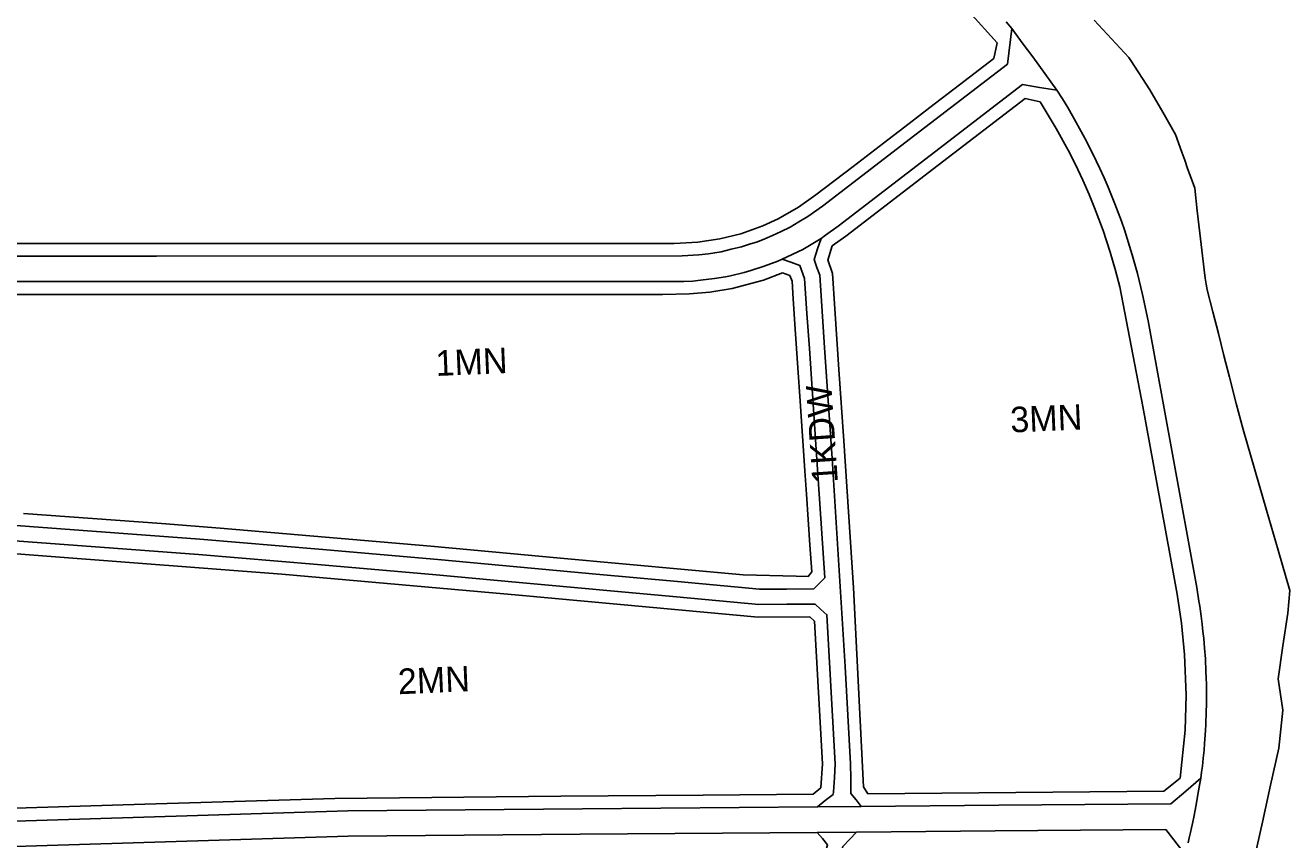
# Model space of a CAD drawing. Extents: x 7418021 to 7419743, y 5540231 to 5541685.
# Drawn here: x 7419247.1 to 7419743, y 5541025.9 to 5541345.6 of the extents above; entities that cross this region are included whole.
import ezdxf

# ---------------------------------------------------------------- set-up
doc = ezdxf.new("R2010")
doc.units = 0
for name, color, linetype in [('linie_rozgraniczajace', 7, 'Continuous'), ('linie_zabudowy_nieprzekraczalne', 7, 'Continuous'), ('oznaczenia_przeznaczen', 7, 'Continuous')]:
    doc.layers.add(name, color=color, linetype=linetype)

msp = doc.modelspace()

# ---------------------------------------------------------------- linework, layer by layer
at = {"layer": 'linie_rozgraniczajace'}
for points in [[(7419631.75, 5541346.86), (7419633.97, 5541344.26), (7419632.27, 5541330.34), (7419596.02, 5541302.47), (7419559.77, 5541274.61), (7419553.96, 5541270.48), (7419550.51, 5541268.42), (7419547.06, 5541266.36), (7419543.61, 5541264.67), (7419540.15, 5541262.98), (7419537.19, 5541261.79), (7419534.23, 5541260.6), (7419531.08, 5541259.59), (7419527.94, 5541258.57), (7419523.97, 5541257.62), (7419520, 5541256.67), (7419517.51, 5541256.26), (7419515.02, 5541255.84), (7419511.27, 5541255.47), (7419504.69, 5541255.01), (7419298.53, 5541254.95), (7419075.49, 5541254.87)], [(7419703.12, 5541024.71), (7419703.59, 5541026.71), (7419704.05, 5541028.71), (7419704.47, 5541030.52), (7419704.89, 5541032.32), (7419705.47, 5541035.46), (7419706.1, 5541038.89), (7419706.66, 5541041.98), (7419706.96, 5541043.61), (7419707.51, 5541046.59), (7419708.15, 5541050.07), (7419708.45, 5541052.45), (7419708.75, 5541054.84), (7419709.07, 5541057.94), (7419709.39, 5541061.04), (7419709.6, 5541063.73), (7419709.95, 5541068.8), (7419710.09, 5541071.18), (7419710.27, 5541076.32), (7419710.31, 5541078.79), (7419710.32, 5541084.06), (7419710.3, 5541086.86), (7419710.23, 5541089.41), (7419710.15, 5541091.96), (7419709.9, 5541096.87), (7419709.6, 5541101.12), (7419709.27, 5541104.88), (7419708.97, 5541107.68), (7419708.67, 5541110.48), (7419708.27, 5541113.65), (7419707.72, 5541117.53), (7419707.39, 5541119.59), (7419706.5, 5541124.88), (7419696.97, 5541177.21), (7419687.43, 5541229.54), (7419685.31, 5541239.93), (7419683.32, 5541248.08), (7419681.26, 5541255.49), (7419678.13, 5541265.27), (7419676.95, 5541268.73), (7419675.69, 5541272.12), (7419674.42, 5541275.5), (7419673.11, 5541278.74), (7419671.8, 5541281.97), (7419670.19, 5541285.63), (7419668.57, 5541289.28), (7419667.11, 5541292.34), (7419663.36, 5541299.83), (7419659.11, 5541307.71), (7419655.99, 5541313.27), (7419653.83, 5541316.68), (7419651.67, 5541320.09), (7419646.99, 5541326.58), (7419642.28, 5541333.11), (7419638.12, 5541338.69), (7419633.97, 5541344.26), (7419631.75, 5541346.86)], [(7419666.33, 5541347.56), (7419673.13, 5541340.23), (7419679.92, 5541332.9), (7419680.74, 5541331.7), (7419688.16, 5541320.18), (7419693.18, 5541311.45), (7419698.21, 5541302.72), (7419700.66, 5541295.81), (7419701.8, 5541292.6), (7419702.94, 5541289.4), (7419704.33, 5541285.49), (7419705.72, 5541281.59), (7419706.74, 5541272.76), (7419707.76, 5541263.94), (7419708.78, 5541255.12), (7419709.79, 5541246.29), (7419710.23, 5541244), (7419710.66, 5541241.7), (7419712.83, 5541233.14), (7419714.99, 5541224.58), (7419717.16, 5541216.01), (7419719.33, 5541207.45), (7419722.03, 5541197.17), (7419724.73, 5541186.88), (7419729.29, 5541171.09), (7419733.85, 5541155.31), (7419738.42, 5541139.52), (7419742.98, 5541123.73), (7419742.19, 5541114.89), (7419740.31, 5541101.99), (7419738.43, 5541089.08), (7419739.33, 5541082.91), (7419740.24, 5541076.74), (7419739.46, 5541069.3), (7419738.68, 5541061.86), (7419735.47, 5541047.35), (7419732.26, 5541032.84), (7419729.06, 5541018.33)], [(7419075.49, 5541254.87), (7419298.53, 5541254.95), (7419504.69, 5541255.01), (7419511.27, 5541255.47), (7419515.02, 5541255.84), (7419517.51, 5541256.26), (7419520, 5541256.67), (7419523.97, 5541257.62), (7419527.94, 5541258.57), (7419531.08, 5541259.59), (7419534.23, 5541260.6), (7419537.19, 5541261.79), (7419540.15, 5541262.98), (7419543.61, 5541264.67), (7419547.06, 5541266.36), (7419550.51, 5541268.42), (7419553.96, 5541270.48), (7419559.77, 5541274.61), (7419596.02, 5541302.47), (7419632.27, 5541330.34), (7419633.97, 5541344.26)], [(7419633.97, 5541344.26), (7419638.12, 5541338.69), (7419642.28, 5541333.11), (7419646.99, 5541326.58), (7419651.67, 5541320.09), (7419644.92, 5541321.18), (7419638.17, 5541322.26), (7419602.02, 5541294.47), (7419565.87, 5541266.68), (7419560.96, 5541263.14), (7419559.19, 5541261.92), (7419552.09, 5541257.55), (7419543.91, 5541253.74), (7419542.22, 5541253.03), (7419536.84, 5541250.96), (7419531.66, 5541249.27), (7419529.1, 5541248.52), (7419523.62, 5541247.2), (7419521.68, 5541246.83), (7419517.4, 5541246.11), (7419511.98, 5541245.46), (7419508.9, 5541245.16), (7419505.38, 5541245.04), (7419501.87, 5541244.93), (7419295.55, 5541244.94), (7419089.24, 5541244.96)], [(7419213.55, 5541151.46), (7419248.73, 5541148.79), (7419282.14, 5541146.33), (7419315.55, 5541143.88), (7419362.2, 5541139.88), (7419408.86, 5541135.88), (7419439.9, 5541133.01), (7419470.94, 5541130.15), (7419502.96, 5541127.2), (7419534.99, 5541124.25), (7419545.64, 5541124.31), (7419556.3, 5541124.36), (7419558.48, 5541126.52), (7419560.66, 5541128.67), (7419557.55, 5541175.19), (7419554.6, 5541218.67), (7419553.67, 5541232.43), (7419552.74, 5541246.19), (7419550.86, 5541251.33), (7419547.39, 5541252.53), (7419543.91, 5541253.74), (7419552.09, 5541257.55), (7419559.19, 5541261.92), (7419557.84, 5541257.77), (7419556.43, 5541253.58), (7419557.55, 5541250.51), (7419558.67, 5541247.44), (7419560.59, 5541219.08), (7419563.54, 5541175.57), (7419568.62, 5541093.87), (7419570.77, 5541055.67), (7419570.81, 5541049.88), (7419570.85, 5541044.11), (7419572.9, 5541041.53), (7419574.94, 5541038.96), (7419557.78, 5541038.81), (7419560.87, 5541041.25), (7419563.96, 5541043.7), (7419564.09, 5541044.7), (7419564.42, 5541050.19), (7419564.76, 5541055.68), (7419561.47, 5541114.23), (7419559.16, 5541116.3), (7419556.85, 5541118.37), (7419545.79, 5541118.31), (7419534.73, 5541118.25), (7419502.56, 5541121.21), (7419439.35, 5541127.04), (7419408.32, 5541129.9), (7419361.7, 5541133.9), (7419315.07, 5541137.9), (7419281.68, 5541140.35), (7419248.28, 5541142.8), (7419213.1, 5541145.48)], [(7419089.24, 5541244.96), (7419295.55, 5541244.94), (7419501.87, 5541244.93), (7419505.38, 5541245.04), (7419508.9, 5541245.16), (7419511.98, 5541245.46), (7419517.4, 5541246.11), (7419521.68, 5541246.83), (7419523.62, 5541247.2), (7419529.1, 5541248.52), (7419531.66, 5541249.27), (7419536.84, 5541250.96), (7419542.22, 5541253.03), (7419543.91, 5541253.74), (7419547.39, 5541252.53), (7419550.86, 5541251.33), (7419552.74, 5541246.19), (7419553.67, 5541232.43), (7419554.6, 5541218.67), (7419557.55, 5541175.19), (7419560.66, 5541128.67), (7419558.48, 5541126.52), (7419556.3, 5541124.36), (7419545.64, 5541124.31), (7419534.99, 5541124.25), (7419502.96, 5541127.2), (7419470.94, 5541130.15), (7419439.9, 5541133.01), (7419408.86, 5541135.88), (7419362.2, 5541139.88), (7419315.55, 5541143.88), (7419282.14, 5541146.33), (7419248.73, 5541148.79), (7419213.55, 5541151.46)], [(7419213.1, 5541145.48), (7419248.28, 5541142.8), (7419281.68, 5541140.35), (7419315.07, 5541137.9), (7419361.7, 5541133.9), (7419408.32, 5541129.9), (7419439.35, 5541127.04), (7419502.56, 5541121.21), (7419534.73, 5541118.25), (7419545.79, 5541118.31), (7419556.85, 5541118.37), (7419559.16, 5541116.3), (7419561.47, 5541114.23), (7419564.76, 5541055.68), (7419564.42, 5541050.19), (7419564.09, 5541044.7), (7419563.96, 5541043.7), (7419560.87, 5541041.25), (7419557.78, 5541038.81), (7419465.69, 5541038.04), (7419373.59, 5541037.27), (7419234.58, 5541032.97)], [(7419234.58, 5541032.97), (7419373.59, 5541037.27), (7419465.69, 5541038.04), (7419557.78, 5541038.81), (7419574.94, 5541038.96), (7419628.91, 5541039.41), (7419696.37, 5541039.97), (7419702.26, 5541045.02), (7419708.15, 5541050.07), (7419707.51, 5541046.59), (7419706.96, 5541043.61), (7419706.66, 5541041.98), (7419706.1, 5541038.89), (7419705.47, 5541035.46), (7419704.89, 5541032.32), (7419704.47, 5541030.52), (7419704.05, 5541028.71), (7419703.59, 5541026.71), (7419703.12, 5541024.71)], [(7419702.04, 5541020.06), (7419694.39, 5541029.96), (7419627.51, 5541029.4), (7419573.14, 5541028.94), (7419557.71, 5541028.81), (7419464.79, 5541028.03), (7419373.79, 5541027.27), (7419234.54, 5541023)], [(7419561.78, 5541023.94), (7419559.74, 5541026.38), (7419557.71, 5541028.81), (7419573.14, 5541028.94), (7419570.45, 5541026.08), (7419567.76, 5541023.22)]]:
    msp.add_lwpolyline(points, dxfattribs=at)
for points in [[(7419559.19, 5541261.92), (7419560.96, 5541263.14), (7419565.87, 5541266.68), (7419602.02, 5541294.47), (7419638.17, 5541322.26), (7419644.92, 5541321.18), (7419651.67, 5541320.09), (7419653.83, 5541316.68), (7419655.99, 5541313.27), (7419659.11, 5541307.71), (7419663.36, 5541299.83), (7419667.11, 5541292.34), (7419668.57, 5541289.28), (7419670.19, 5541285.63), (7419671.8, 5541281.97), (7419673.11, 5541278.74), (7419674.42, 5541275.5), (7419675.69, 5541272.12), (7419676.95, 5541268.73), (7419678.13, 5541265.27), (7419681.26, 5541255.49), (7419683.32, 5541248.08), (7419685.31, 5541239.93), (7419687.43, 5541229.54), (7419696.97, 5541177.21), (7419706.5, 5541124.88), (7419707.39, 5541119.59), (7419707.72, 5541117.53), (7419708.27, 5541113.65), (7419708.67, 5541110.48), (7419708.97, 5541107.68), (7419709.27, 5541104.88), (7419709.6, 5541101.12), (7419709.9, 5541096.87), (7419710.15, 5541091.96), (7419710.23, 5541089.41), (7419710.3, 5541086.86), (7419710.32, 5541084.06), (7419710.31, 5541078.79), (7419710.27, 5541076.32), (7419710.09, 5541071.18), (7419709.95, 5541068.8), (7419709.6, 5541063.73), (7419709.39, 5541061.04), (7419709.07, 5541057.94), (7419708.75, 5541054.84), (7419708.45, 5541052.45), (7419708.15, 5541050.07), (7419702.26, 5541045.02), (7419696.37, 5541039.97), (7419628.91, 5541039.41), (7419574.94, 5541038.96), (7419572.9, 5541041.53), (7419570.85, 5541044.11), (7419570.81, 5541049.88), (7419570.77, 5541055.67), (7419568.62, 5541093.87), (7419563.54, 5541175.57), (7419560.59, 5541219.08), (7419558.67, 5541247.44), (7419557.55, 5541250.51), (7419556.43, 5541253.58), (7419557.84, 5541257.77)], [(7419095.29, 5541018.74), (7419234.54, 5541023), (7419373.79, 5541027.27), (7419464.79, 5541028.03), (7419557.71, 5541028.81), (7419559.74, 5541026.38), (7419561.78, 5541023.94), (7419553.94, 5540993.88), (7419546.61, 5540965.74), (7419543.38, 5540963.37), (7419540.14, 5540961), (7419488.96, 5540958.13), (7419385.59, 5540952.23), (7419282.22, 5540946.32), (7419257.39, 5540947.92), (7419232.55, 5540949.52), (7419183.71, 5540952.61), (7419134.88, 5540955.7), (7419086.04, 5540958.8), (7419083.17, 5540961.6), (7419080.29, 5540964.41), (7419084.37, 5541008.48)], [(7419573.14, 5541028.94), (7419627.51, 5541029.4), (7419694.39, 5541029.96), (7419702.04, 5541020.06), (7419682.92, 5540950.48), (7419663.99, 5540881.59), (7419663.17, 5540878.7), (7419662.77, 5540877.34), (7419662.54, 5540876.55), (7419655.53, 5540871.26), (7419648.52, 5540865.96), (7419530.9, 5540861.18), (7419527.93, 5540864.25), (7419524.97, 5540867.31), (7419532.73, 5540892.9), (7419540.49, 5540918.5), (7419543.88, 5540931.49), (7419547.26, 5540944.48), (7419551.14, 5540959.4), (7419559.45, 5540991.31), (7419567.76, 5541023.22), (7419570.45, 5541026.08)]]:
    msp.add_lwpolyline(points, close=True, dxfattribs=at)
at = {"layer": 'linie_zabudowy_nieprzekraczalne'}
for points in [[(7419628.25, 5541338.65), (7419617.19, 5541351.01)], [(7419626.9, 5541332.52), (7419628.25, 5541338.65)], [(7419613.42, 5541322.16), (7419626.9, 5541332.52)], [(7419601.91, 5541313.31), (7419613.42, 5541322.16)], [(7419639.21, 5541316.76), (7419605.17, 5541290.59)], [(7419645.11, 5541315.51), (7419639.21, 5541316.76)], [(7419651.41, 5541305.09), (7419645.11, 5541315.51)], [(7419593.75, 5541307.04), (7419601.91, 5541313.31)], [(7419583.74, 5541299.34), (7419593.75, 5541307.04)], [(7419656.07, 5541296.52), (7419651.41, 5541305.09)], [(7419571.83, 5541290.18), (7419583.74, 5541299.34)], [(7419658.92, 5541290.95), (7419656.07, 5541296.52)], [(7419557.2, 5541278.94), (7419571.83, 5541290.18)], [(7419605.17, 5541290.59), (7419568.92, 5541262.72)], [(7419661.86, 5541284.7), (7419658.92, 5541290.95)], [(7419664.33, 5541279.08), (7419661.86, 5541284.7)], [(7419550.32, 5541274.13), (7419557.2, 5541278.94)], [(7419666.44, 5541273.9), (7419664.33, 5541279.08)], [(7419542.36, 5541269.63), (7419550.32, 5541274.13)], [(7419669.78, 5541264.97), (7419666.44, 5541273.9)], [(7419527.7, 5541263.75), (7419536.42, 5541266.87)], [(7419536.42, 5541266.87), (7419542.36, 5541269.63)], [(7419501.55, 5541259.93), (7419510.89, 5541260.46)], [(7419510.89, 5541260.46), (7419519.47, 5541261.69)], [(7419519.47, 5541261.69), (7419527.7, 5541263.75)], [(7419568.92, 5541262.72), (7419563.52, 5541258.95)], [(7419672.57, 5541256.52), (7419669.78, 5541264.97)], [(7419235.07, 5541259.95), (7419266.19, 5541259.95)], [(7419266.19, 5541259.95), (7419294.71, 5541259.95)], [(7419294.71, 5541259.95), (7419321.43, 5541259.95)], [(7419321.43, 5541259.95), (7419350.82, 5541259.94)], [(7419350.82, 5541259.94), (7419370.74, 5541259.94)], [(7419370.74, 5541259.94), (7419404.93, 5541259.94)], [(7419404.93, 5541259.94), (7419437.49, 5541259.93)], [(7419437.49, 5541259.93), (7419459.56, 5541259.93)], [(7419459.56, 5541259.93), (7419482.05, 5541259.93)], [(7419482.05, 5541259.93), (7419501.55, 5541259.93)], [(7419563.52, 5541258.95), (7419561.84, 5541253.35)], [(7419674.69, 5541249.27), (7419672.57, 5541256.52)], [(7419561.79, 5541253.48), (7419563.64, 5541248.1)], [(7419536.62, 5541245.58), (7419524.34, 5541242.25)], [(7419544.08, 5541248.39), (7419536.62, 5541245.58)], [(7419546.98, 5541247.38), (7419544.08, 5541248.39)], [(7419547.8, 5541245.14), (7419546.98, 5541247.38)], [(7419563.64, 5541248.1), (7419564.58, 5541234.25)], [(7419676.36, 5541242.91), (7419674.69, 5541249.27)], [(7419515.6, 5541240.79), (7419507.59, 5541240.12)], [(7419524.34, 5541242.25), (7419515.6, 5541240.79)], [(7419548.28, 5541238.13), (7419547.8, 5541245.14)], [(7419685.43, 5541195.93), (7419676.36, 5541242.91)], [(7419277.44, 5541239.94), (7419242.13, 5541239.95)], [(7419303.19, 5541239.94), (7419277.44, 5541239.94)], [(7419364.21, 5541239.94), (7419303.19, 5541239.94)], [(7419382.79, 5541239.94), (7419364.21, 5541239.94)], [(7419396.93, 5541239.94), (7419382.79, 5541239.94)], [(7419416.55, 5541239.93), (7419396.93, 5541239.94)], [(7419434.53, 5541239.93), (7419416.55, 5541239.93)], [(7419460.94, 5541239.93), (7419434.53, 5541239.93)], [(7419481.41, 5541239.93), (7419460.94, 5541239.93)], [(7419496.95, 5541239.93), (7419481.41, 5541239.93)], [(7419507.59, 5541240.12), (7419496.95, 5541239.93)], [(7419549.08, 5541226.31), (7419548.28, 5541238.13)], [(7419564.58, 5541234.25), (7419566.19, 5541210.45)], [(7419550.1, 5541211.14), (7419549.08, 5541226.31)], [(7419550.99, 5541198.02), (7419550.1, 5541211.14)], [(7419566.19, 5541210.45), (7419568.08, 5541182.44)], [(7419552.84, 5541170.73), (7419550.99, 5541198.02)], [(7419692.32, 5541158.09), (7419685.43, 5541195.93)], [(7419568.08, 5541182.44), (7419571.91, 5541124.72)], [(7419553.46, 5541161.59), (7419552.84, 5541170.73)], [(7419554.81, 5541141.62), (7419553.46, 5541161.59)], [(7419696.48, 5541135.24), (7419692.32, 5541158.09)], [(7419246.39, 5541153.98), (7419273.49, 5541151.98)], [(7419273.49, 5541151.98), (7419300.55, 5541150)], [(7419300.55, 5541150), (7419323.56, 5541148.21)], [(7419323.56, 5541148.21), (7419406.2, 5541141.12)], [(7419347.74, 5541130.08), (7419165.02, 5541144.17)], [(7419555.53, 5541131.05), (7419554.81, 5541141.62)], [(7419406.2, 5541141.12), (7419437.22, 5541138.28)], [(7419437.22, 5541138.28), (7419455.57, 5541136.59)], [(7419455.57, 5541136.59), (7419507.02, 5541131.85)], [(7419507.02, 5541131.85), (7419528.59, 5541129.86)], [(7419698.84, 5541122.27), (7419696.48, 5541135.24)], [(7419440.7, 5541121.89), (7419347.74, 5541130.08)], [(7419528.59, 5541129.86), (7419549.39, 5541129.33)], [(7419549.39, 5541129.33), (7419554.12, 5541129.24)], [(7419554.12, 5541129.24), (7419555.53, 5541131.05)], [(7419491.86, 5541117.18), (7419440.7, 5541121.89)], [(7419571.91, 5541124.72), (7419575.84, 5541046.71)], [(7419700.56, 5541110.87), (7419698.84, 5541122.27)], [(7419534.52, 5541113.25), (7419491.86, 5541117.18)], [(7419554.82, 5541113.36), (7419534.52, 5541113.25)], [(7419556.61, 5541111.74), (7419554.82, 5541113.36)], [(7419559.75, 5541055.73), (7419556.61, 5541111.74)], [(7419701.77, 5541098.56), (7419700.56, 5541110.87)], [(7419702.34, 5541082.6), (7419701.77, 5541098.56)], [(7419701.95, 5541068.93), (7419702.34, 5541082.6)], [(7419700.02, 5541050.07), (7419701.95, 5541068.93)], [(7419559.11, 5541046.23), (7419559.75, 5541055.73)], [(7419693.66, 5541044.95), (7419700.02, 5541050.07)], [(7419293.98, 5541039.83), (7419368.47, 5541042.11)], [(7419368.47, 5541042.11), (7419457.2, 5541042.97)], [(7419457.2, 5541042.97), (7419512.95, 5541043.44)], [(7419512.95, 5541043.44), (7419556.15, 5541043.8)], [(7419556.15, 5541043.8), (7419559.11, 5541046.23)], [(7419575.84, 5541046.71), (7419577.58, 5541043.98)], [(7419577.58, 5541043.98), (7419693.66, 5541044.95)], [(7419234.68, 5541038.02), (7419293.98, 5541039.83)]]:
    msp.add_lwpolyline(points, dxfattribs=at)

# ---------------------------------------------------------------- texts
at = {"layer": 'oznaczenia_przeznaczen'}
for s, rotation, p in [('1MN', 2.396, (7419408.21, 5541207.9)), ('1KDW', 93.8722, (7419565.81, 5541166.14)), ('3MN', 2.396, (7419633.61, 5541185.72)), ('2MN', 2.4191, (7419393.45, 5541082.99))]:
    msp.add_text(s, height=10, rotation=rotation, dxfattribs=at).set_placement(p)

doc.saveas('drawing.dxf')
